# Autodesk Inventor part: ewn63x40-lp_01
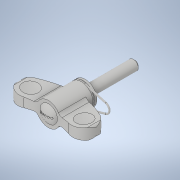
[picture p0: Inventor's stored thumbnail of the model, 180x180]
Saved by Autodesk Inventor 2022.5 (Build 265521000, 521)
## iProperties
Created: 2021-08
Part Number: ewn63x40-lp_01
Material: 一般
Document SubType Name: Modeling
Designer: ImaoCorp
Density: 1 g/cm^3
Appearance: 既定
Author: ImaoCorp
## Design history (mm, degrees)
feature "ewn63x40-lp_01"
node "ソリッド1"
